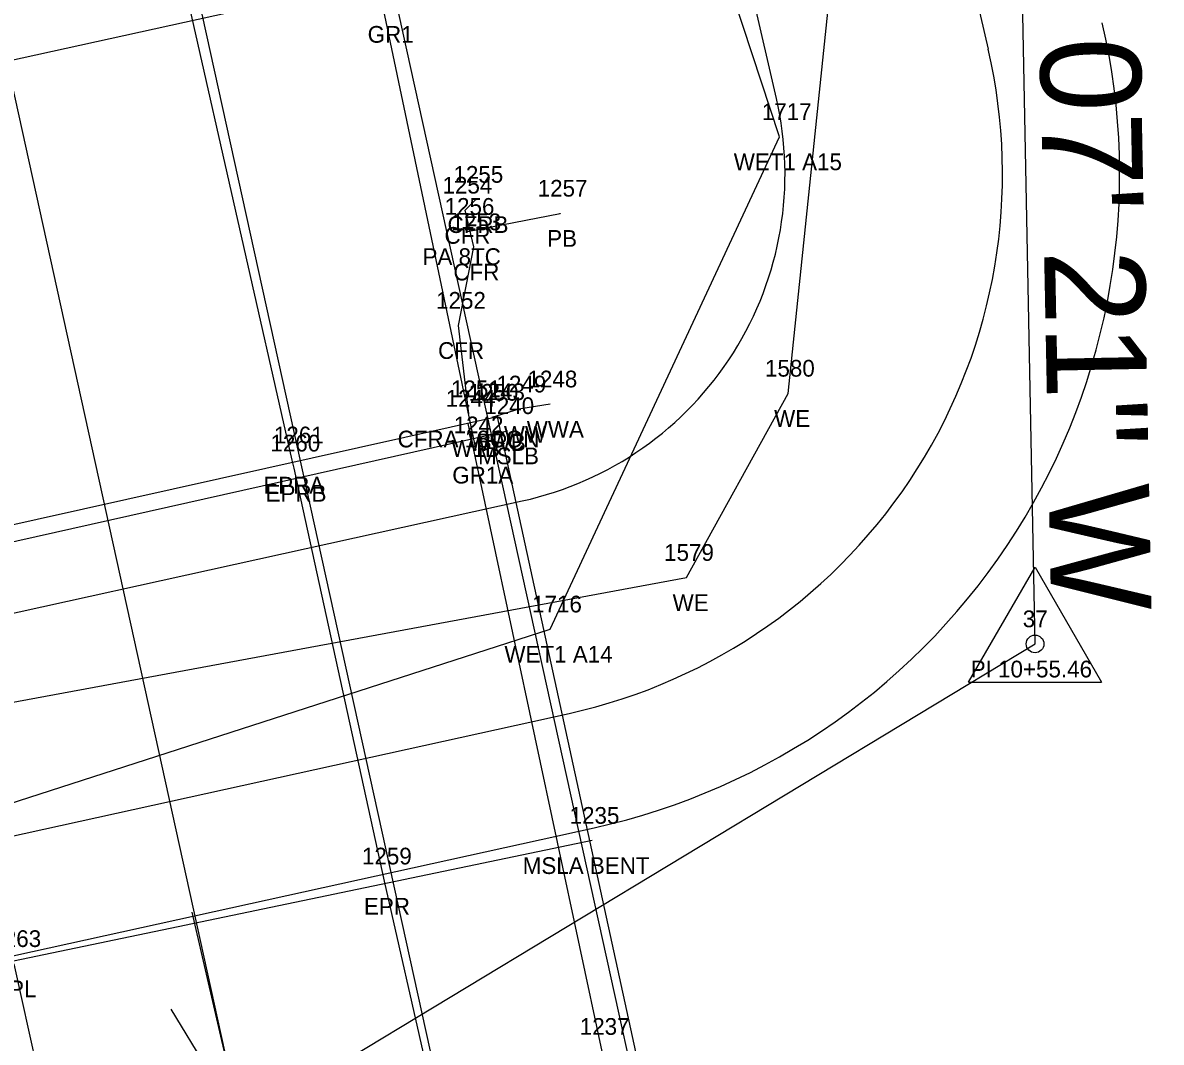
# Model space of a CAD drawing. Extents: x 2521558 to 2549345, y 854846 to 887632.
# Drawn here: x 2523776.7 to 2523844.7, y 885124.5 to 885185.4 of the extents above; entities that cross this region are included whole.
import ezdxf

# ---------------------------------------------------------------- set-up
doc = ezdxf.new("R2010")
doc.units = 0
for name, color, linetype in [('RD_EV_JW', 7, 'Continuous'), ('RD_EX_BldgApp', 7, 'Continuous'), ('RD_EX_BldgApp_txCode', 7, 'Continuous'), ('RD_EX_Bridge', 7, 'Continuous'), ('RD_EX_Bridge_txCode', 7, 'Continuous'), ('RD_EX_Conc', 7, 'Continuous'), ('RD_EX_Conc_txCode', 7, 'Continuous'), ('RD_EX_DR_Pipe', 7, 'Continuous'), ('RD_EX_DR_Pipe_txCode', 7, 'Continuous'), ('RD_EX_GuardRail', 7, 'Continuous'), ('RD_EX_GuardRail_txCode', 7, 'Continuous'), ('RD_EX_H2O', 7, 'Continuous'), ('RD_EX_H2O_txCode', 7, 'Continuous'), ('RD_EX_H2O_WetLd_txCode', 7, 'Continuous'), ('RD_EX_Misc', 7, 'Continuous'), ('RD_EX_Misc_txCode', 7, 'Continuous'), ('RD_EX_Road', 7, 'Continuous'), ('RD_EX_Road_txCode', 7, 'Continuous'), ('RD_HC_Cl', 7, 'Continuous'), ('RD_HC_Data', 7, 'Continuous'), ('RD_HC_Data_Tic', 7, 'Continuous'), ('RD_HC_txCode', 7, 'Continuous'), ('RD_PD_BCA', 7, 'Continuous'), ('RD_PD_Bridge', 7, 'Continuous'), ('RD_PD_CstnLmt', 7, 'Continuous'), ('RD_PD_DR_ErosCtrl', 7, 'Continuous'), ('RD_PD_Final_TrvlWay', 7, 'Continuous'), ('RD_PD_RW', 7, 'Continuous'), ('RD_SMD_Locator', 7, 'Continuous')]:
    doc.layers.add(name, color=color, linetype=linetype)

msp = doc.modelspace()

# ---------------------------------------------------------------- linework, layer by layer
at = {"layer": 'RD_EV_JW'}
msp.add_lwpolyline([(2523761.167, 885134.03), (2523808.209, 885149.207), (2523821.914, 885178.637), (2523802.851, 885236.548), (2523777.81, 885305.562), (2523748.196, 885444.322), (2523730.68, 885516.876), (2523708.637, 885617.3), (2523698.714, 885662.019), (2523727.827, 885665.815), (2523757.297, 885671.751)], dxfattribs=at)
at = {"layer": 'RD_EX_BldgApp'}
msp.add_lwpolyline([(2523819.439, 885087.441), (2523811.319, 885123.961), (2523803.308, 885161.503)], dxfattribs=at)
at = {"layer": 'RD_EX_Bridge'}
for points in [[(2523808.195, 885162.657), (2523806.339, 885162.355), (2523804.708, 885161.862)], [(2523774.906, 885077.596), (2523821.197, 885087.829), (2523805.064, 885161.895), (2523758.145, 885151.437), (2523774.906, 885077.596)]]:
    msp.add_lwpolyline(points, dxfattribs=at)
at = {"layer": 'RD_EX_Conc'}
msp.add_lwpolyline([(2523803.338, 885162.07), (2523802.732, 885167.359), (2523803.647, 885172.05), (2523803.117, 885174.241), (2523803.77, 885174.887)], dxfattribs=at)
at = {"layer": 'RD_EX_DR_Pipe'}
msp.add_line((2523803.266, 885172.973), (2523808.803, 885174.059), dxfattribs=at)
at = {"layer": 'RD_EX_GuardRail'}
msp.add_lwpolyline([(2523803.786, 885159.912), (2523798.239, 885186.256), (2523787.795, 885236.892)], dxfattribs=at)
at = {"layer": 'RD_EX_H2O'}
msp.add_lwpolyline([(2523738.909, 885147.498), (2523743.695, 885138.843), (2523816.359, 885152.29), (2523822.427, 885163.299), (2523826.928, 885206.612)], dxfattribs=at)
at = {"layer": 'RD_EX_Misc'}
for p, q in [((2523758.452, 885150.465), (2523805.656, 885161.063)), ((2523810.713, 885136.574), (2523763.829, 885126.803))]:
    msp.add_line(p, q, dxfattribs=at)
at = {"layer": 'RD_EX_Road'}
for p, q in [((2523792.777, 885159.311), (2523771.239, 885254.787)), ((2523792.894, 885158.826), (2523792.777, 885159.311)), ((2523798.302, 885134.145), (2523792.894, 885158.826)), ((2523803.791, 885109.941), (2523798.302, 885134.145)), ((2523781.516, 885104.768), (2523776.178, 885129.21))]:
    msp.add_line(p, q, dxfattribs=at)
at = {"layer": 'RD_HC_Cl'}
for p, q in [((2523641.165, 885794.201), (2524197.759, 883266.557)), ((2523837.18, 885148.323), (2523836.106, 885203.1)), ((2523672.044, 885048.634), (2523837.18, 885148.323))]:
    msp.add_line(p, q, dxfattribs=at)
at = {"layer": 'RD_HC_Data'}
for p, q in [((2523833.209, 885146.03), (2523837.181, 885152.909)), ((2523837.181, 885152.909), (2523841.149, 885146.03)), ((2523833.209, 885146.03), (2523841.149, 885146.03))]:
    msp.add_line(p, q, dxfattribs=at)
msp.add_circle((2523837.18, 885148.323), 0.529, dxfattribs=at)
at = {"layer": 'RD_HC_Data_Tic'}
msp.add_line((2523789.692, 885119.656), (2523785.558, 885126.504), dxfattribs=at)
at = {"layer": 'RD_PD_BCA'}
msp.add_lwpolyline([(2523762.054, 885126.595), (2523810.84, 885137.338)], dxfattribs=at)
msp.add_arc((2523802.238, 885176.402), 40, 282.41848, 13.07237, dxfattribs=at)
at = {"layer": 'RD_PD_Bridge'}
for points in [[(2523798.673, 885188.194), (2523752.772, 885178.086)], [(2523826.629, 885061.235), (2523798.673, 885188.194)]]:
    msp.add_lwpolyline(points, dxfattribs=at)
at = {"layer": 'RD_PD_CstnLmt'}
msp.add_line((2523810.511, 885229.196), (2523821.719, 885180.926), dxfattribs=at)
msp.add_lwpolyline([(2523757.753, 885146.127), (2523806.539, 885156.87)], dxfattribs=at)
msp.add_arc((2523802.238, 885176.402), 20, 282.41848, 13.07237, dxfattribs=at)
at = {"layer": 'RD_PD_DR_ErosCtrl'}
msp.add_line((2523823.174, 885232.137), (2523834.383, 885183.866), dxfattribs=at)
msp.add_lwpolyline([(2523760.548, 885133.431), (2523809.334, 885144.174)], dxfattribs=at)
msp.add_arc((2523802.238, 885176.402), 33, 282.41848, 13.07237, dxfattribs=at)
at = {"layer": 'RD_PD_Final_TrvlWay'}
msp.add_line((2523741.744, 885393.246), (2524015.933, 884148.078), dxfattribs=at)
at = {"layer": 'RD_PD_RW'}
msp.add_line((2523789.736, 885119.635), (2523786.8, 885132.299), dxfattribs=at)
at = {"layer": 'RD_SMD_Locator'}
for centre in [(2523821.914, 885178.637), (2523803.77, 885174.887), (2523803.117, 885174.241), (2523808.803, 885174.059), (2523803.266, 885172.973), (2523803.647, 885172.05), (2523802.732, 885167.359), (2523822.427, 885163.299), (2523806.339, 885162.355), (2523808.195, 885162.657), (2523803.338, 885162.07), (2523804.708, 885161.862), (2523805.064, 885161.895), (2523803.308, 885161.503), (2523805.656, 885161.063), (2523803.786, 885159.912), (2523792.777, 885159.311), (2523792.894, 885158.826), (2523816.359, 885152.29), (2523808.209, 885149.207), (2523837.18, 885148.323), (2523810.713, 885136.574), (2523798.302, 885134.145)]:
    msp.add_circle(centre, 0.001, dxfattribs=at)

# ---------------------------------------------------------------- texts
at = {"layer": 'RD_EX_BldgApp_txCode'}
for s, p in [('1244', (2523801.961, 885162.503)), ('W1B', (2523802.3, 885159.503)), ('1237', (2523809.973, 885124.961))]:
    msp.add_text(s, height=1, dxfattribs=at).set_placement(p)
at = {"layer": 'RD_EX_Bridge_txCode'}
for s, p in [('1249', (2523804.993, 885163.355)), ('1248', (2523806.848, 885163.657)), ('1250', (2523803.323, 885162.862)), ('1243', (2523803.718, 885162.895)), ('WWA', (2523806.801, 885160.657)), ('WWB', (2523803.33, 885159.862)), ('BRC', (2523803.812, 885159.895)), ('WW', (2523805.434, 885160.355))]:
    msp.add_text(s, height=1, dxfattribs=at).set_placement(p)
at = {"layer": 'RD_EX_Conc_txCode'}
for s, p in [('1255', (2523802.423, 885175.887)), ('1254', (2523801.77, 885175.241)), ('CFRB', (2523802.069, 885172.887)), ('1253', (2523802.301, 885173.05)), ('CFR', (2523801.888, 885172.241)), ('CFR', (2523802.419, 885170.05)), ('1252', (2523801.386, 885168.359)), ('CFR', (2523801.504, 885165.359)), ('1251', (2523802.275, 885163.07)), ('CFRA 18CON', (2523799.086, 885160.07))]:
    msp.add_text(s, height=1, dxfattribs=at).set_placement(p)
at = {"layer": 'RD_EX_DR_Pipe_txCode'}
for s, p in [('1257', (2523807.457, 885175.059)), ('1256', (2523801.896, 885173.973)), ('PB', (2523808.024, 885172.059)), ('PA 8TC', (2523800.573, 885170.973))]:
    msp.add_text(s, height=1, dxfattribs=at).set_placement(p)
at = {"layer": 'RD_EX_GuardRail_txCode'}
for s, p in [('GR1', (2523797.294, 885184.256)), ('1242', (2523802.439, 885160.912)), ('GR1A', (2523802.353, 885157.912))]:
    msp.add_text(s, height=1, dxfattribs=at).set_placement(p)
at = {"layer": 'RD_EX_H2O_txCode'}
for s, p in [('1580', (2523821.041, 885164.299)), ('WE', (2523821.588, 885161.299)), ('1579', (2523815.013, 885153.29)), ('WE', (2523815.521, 885150.29))]:
    msp.add_text(s, height=1, dxfattribs=at).set_placement(p)
at = {"layer": 'RD_EX_H2O_WetLd_txCode'}
for s, p in [('1717', (2523820.851, 885179.637)), ('WET1 A15', (2523819.174, 885176.637)), ('1716', (2523807.123, 885150.207)), ('WET1 A14', (2523805.469, 885147.207))]:
    msp.add_text(s, height=1, dxfattribs=at).set_placement(p)
at = {"layer": 'RD_EX_Misc_txCode'}
for s, p in [('1240', (2523804.27, 885162.063)), ('MSLB', (2523803.892, 885159.063)), ('1235', (2523809.366, 885137.574)), ('MSLA BENT', (2523806.563, 885134.574))]:
    msp.add_text(s, height=1, dxfattribs=at).set_placement(p)
at = {"layer": 'RD_EX_Road_txCode'}
for s, p in [('1260', (2523791.484, 885159.826)), ('1261', (2523791.691, 885160.311)), ('EPRA', (2523791.061, 885157.311)), ('EPRB', (2523791.193, 885156.826)), ('1259', (2523796.956, 885135.145)), ('EPR', (2523797.074, 885132.145)), ('1263', (2523774.808, 885130.21)), ('EPL', (2523774.974, 885127.21))]:
    msp.add_text(s, height=1, dxfattribs=at).set_placement(p)
at = {"layer": 'RD_HC_Data'}
msp.add_text('N 1%%d 07\' 21" W', height=6, rotation=271.12261, dxfattribs=at).set_placement((2523837.119, 885202.44))
at = {"layer": 'RD_HC_txCode'}
for s, p in [('37', (2523836.447, 885149.323)), ('PI 10+55.46', (2523833.337, 885146.323))]:
    msp.add_text(s, height=1, dxfattribs=at).set_placement(p)

doc.saveas('drawing.dxf')
